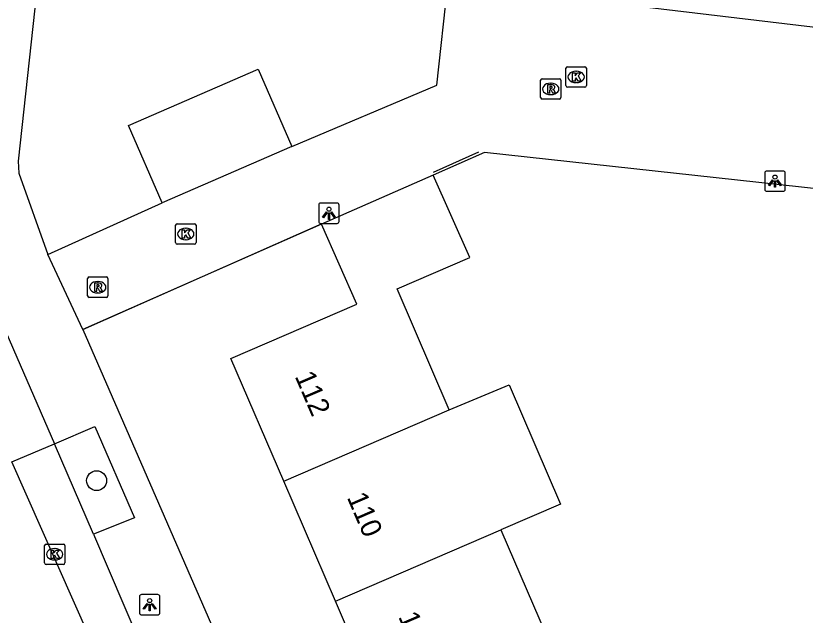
# Model space of a CAD drawing. Extents: x 162026 to 163499, y 387297 to 388169.
# Drawn here: x 162202.16 to 162240.89, y 387912.47 to 387941.9 of the extents above; entities that cross this region are included whole.
import ezdxf

# ---------------------------------------------------------------- set-up
doc = ezdxf.new("R2010")
doc.units = 0
for name, color, linetype in [('IMGEO_Boom', 7, 'Continuous'), ('IMGEO_Kolk', 7, 'Continuous'), ('IMGEO_Lichtpunt', 7, 'Continuous'), ('IMGEO_Muur', 7, 'Continuous'), ('IMGEO_Pand', 7, 'Continuous'), ('IMGEO_Pand_nummerreeks', 7, 'Continuous'), ('IMGEO_Parkeervlak_open', 7, 'Continuous'), ('IMGEO_Rijbaan_lokaal_open', 7, 'Continuous'), ('IMGEO_Rioolput', 7, 'Continuous'), ('IMGEO_Voetpad_open', 7, 'Continuous')]:
    doc.layers.add(name, color=color, linetype=linetype)

msp = doc.modelspace()

# ---------------------------------------------------------------- linework, layer by layer
at = {"layer": 'IMGEO_Boom'}
msp.add_circle((162206.125, 387919.078), 0.489, dxfattribs=at)
at = {"layer": 'IMGEO_Kolk'}
for p, q in [((162229.153, 387938.473), (162229.153, 387939.325)), ((162229.228, 387939.399), (162230.08, 387939.399)), ((162230.154, 387939.325), (162230.154, 387938.473)), ((162229.641, 387939.179), (162229.666, 387939.179)), ((162229.664, 387938.619), (162229.639, 387938.619)), ((162230.08, 387938.399), (162229.228, 387938.399)), ((162210.001, 387930.763), (162210.001, 387931.615)), ((162210.076, 387931.689), (162210.928, 387931.689)), ((162211.002, 387931.615), (162211.002, 387930.763)), ((162210.489, 387931.469), (162210.514, 387931.469)), ((162210.512, 387930.909), (162210.487, 387930.909)), ((162210.928, 387930.689), (162210.076, 387930.689)), ((162203.57, 387915.037), (162203.57, 387915.889)), ((162203.645, 387915.963), (162204.497, 387915.963)), ((162204.058, 387915.743), (162204.083, 387915.743)), ((162204.571, 387915.889), (162204.571, 387915.037)), ((162204.497, 387914.963), (162203.645, 387914.963)), ((162204.081, 387915.183), (162204.056, 387915.183))]:
    msp.add_line(p, q, dxfattribs=at)
for points in [[(162229.153, 387938.473), (162229.153, 387939.325)], [(162229.228, 387939.399), (162230.08, 387939.399)], [(162230.154, 387939.325), (162230.154, 387938.473)], [(162229.474, 387939.099), (162229.597, 387939.099), (162229.597, 387938.948), (162229.727, 387939.099), (162229.891, 387939.099), (162229.745, 387938.948), (162229.898, 387938.699), (162229.746, 387938.699), (162229.661, 387938.863), (162229.597, 387938.796), (162229.597, 387938.699), (162229.474, 387938.699), (162229.474, 387939.099)], [(162230.08, 387938.399), (162229.228, 387938.399)], [(162210.001, 387930.763), (162210.001, 387931.615)], [(162210.076, 387931.689), (162210.928, 387931.689)], [(162211.002, 387931.615), (162211.002, 387930.763)], [(162210.322, 387931.389), (162210.445, 387931.389), (162210.445, 387931.238), (162210.575, 387931.389), (162210.739, 387931.389), (162210.593, 387931.238), (162210.746, 387930.989), (162210.594, 387930.989), (162210.509, 387931.153), (162210.445, 387931.086), (162210.445, 387930.989), (162210.322, 387930.989), (162210.322, 387931.389)], [(162210.928, 387930.689), (162210.076, 387930.689)], [(162203.57, 387915.037), (162203.57, 387915.889)], [(162203.645, 387915.963), (162204.497, 387915.963)], [(162203.891, 387915.663), (162204.014, 387915.663), (162204.014, 387915.512), (162204.144, 387915.663), (162204.308, 387915.663), (162204.162, 387915.512), (162204.315, 387915.263), (162204.163, 387915.263), (162204.078, 387915.427), (162204.014, 387915.36), (162204.014, 387915.263), (162203.891, 387915.263), (162203.891, 387915.663)], [(162204.571, 387915.889), (162204.571, 387915.037)], [(162204.497, 387914.963), (162203.645, 387914.963)]]:
    msp.add_lwpolyline(points, dxfattribs=at)
for centre, start, end in [((162229.23, 387939.323), 91.552, 178.448), ((162229.23, 387939.323), 91.552, 178.448), ((162230.078, 387939.323), 1.552, 88.448), ((162230.078, 387939.323), 1.552, 88.448), ((162229.23, 387938.475), 181.552, 268.448), ((162229.23, 387938.475), 181.552, 268.448), ((162230.078, 387938.475), 271.552, 358.448), ((162230.078, 387938.475), 271.552, 358.448), ((162210.078, 387931.613), 91.552, 178.448), ((162210.078, 387931.613), 91.552, 178.448), ((162210.926, 387931.613), 1.552, 88.448), ((162210.926, 387931.613), 1.552, 88.448), ((162210.078, 387930.765), 181.552, 268.448), ((162210.078, 387930.765), 181.552, 268.448), ((162210.926, 387930.765), 271.552, 358.448), ((162210.926, 387930.765), 271.552, 358.448), ((162203.647, 387915.887), 91.552, 178.448), ((162203.647, 387915.887), 91.552, 178.448), ((162204.495, 387915.887), 1.552, 88.448), ((162204.495, 387915.887), 1.552, 88.448), ((162203.647, 387915.039), 181.552, 268.448), ((162203.647, 387915.039), 181.552, 268.448), ((162204.495, 387915.039), 271.552, 358.448), ((162204.495, 387915.039), 271.552, 358.448)]:
    msp.add_arc(centre, 0.0765, start, end, dxfattribs=at)
for centre, major_axis, ratio, start_param, end_param in [((162229.64, 387938.899), (-0.387, 0.002), 0.722429, 4.712389, 7.853982), ((162229.665, 387938.899), (-0.39, 0.002), 0.717154, 1.570796, 4.712389), ((162210.488, 387931.189), (-0.387, 0.002), 0.722429, 4.712389, 7.853982), ((162210.513, 387931.189), (-0.39, 0.002), 0.717154, 1.570796, 4.712389), ((162204.057, 387915.463), (-0.387, 0.002), 0.722429, 4.712389, 7.853982), ((162204.082, 387915.463), (-0.39, 0.002), 0.717154, 1.570796, 4.712389)]:
    msp.add_ellipse(centre, major_axis=major_axis, ratio=ratio, start_param=start_param, end_param=end_param, dxfattribs=at)
at = {"layer": 'IMGEO_Lichtpunt'}
for p, q in [((162239.814, 387934.281), (162239.006, 387934.281)), ((162239.814, 387934.281), (162239.006, 387934.281)), ((162238.912, 387934.186), (162238.912, 387933.379)), ((162238.912, 387934.186), (162238.912, 387933.379)), ((162239.908, 387933.379), (162239.908, 387934.186)), ((162239.908, 387933.379), (162239.908, 387934.186)), ((162239.006, 387933.285), (162239.814, 387933.285)), ((162239.006, 387933.285), (162239.814, 387933.285)), ((162217.927, 387932.706), (162217.119, 387932.706)), ((162217.927, 387932.706), (162217.119, 387932.706)), ((162217.025, 387932.611), (162217.025, 387931.804)), ((162217.025, 387932.611), (162217.025, 387931.804)), ((162218.021, 387931.804), (162218.021, 387932.611)), ((162218.021, 387931.804), (162218.021, 387932.611)), ((162217.119, 387931.71), (162217.927, 387931.71)), ((162217.119, 387931.71), (162217.927, 387931.71)), ((162208.23, 387913.389), (162208.23, 387912.582)), ((162208.23, 387913.389), (162208.23, 387912.582)), ((162209.132, 387913.484), (162208.324, 387913.484)), ((162209.132, 387913.484), (162208.324, 387913.484)), ((162209.226, 387912.582), (162209.226, 387913.389)), ((162209.226, 387912.582), (162209.226, 387913.389)), ((162208.324, 387912.488), (162209.132, 387912.488)), ((162208.324, 387912.488), (162209.132, 387912.488))]:
    msp.add_line(p, q, dxfattribs=at)
for points in [[(162239.286, 387933.85), (162239.325, 387933.822), (162239.137, 387933.56), (162239.099, 387933.587), (162239.286, 387933.85)], [(162239.498, 387933.822), (162239.536, 387933.849), (162239.723, 387933.587), (162239.684, 387933.559), (162239.498, 387933.822)], [(162239.388, 387933.802), (162239.435, 387933.802), (162239.435, 387933.48), (162239.388, 387933.48), (162239.388, 387933.802)], [(162217.399, 387932.275), (162217.438, 387932.247), (162217.25, 387931.985), (162217.212, 387932.012), (162217.399, 387932.275)], [(162217.501, 387932.227), (162217.548, 387932.227), (162217.548, 387931.905), (162217.501, 387931.905), (162217.501, 387932.227)], [(162217.611, 387932.247), (162217.649, 387932.274), (162217.836, 387932.012), (162217.797, 387931.984), (162217.611, 387932.247)], [(162208.604, 387913.053), (162208.643, 387913.025), (162208.455, 387912.763), (162208.417, 387912.79), (162208.604, 387913.053)], [(162208.706, 387913.005), (162208.753, 387913.005), (162208.753, 387912.683), (162208.706, 387912.683), (162208.706, 387913.005)], [(162208.816, 387913.025), (162208.854, 387913.052), (162209.041, 387912.79), (162209.002, 387912.762), (162208.816, 387913.025)]]:
    msp.add_lwpolyline(points, dxfattribs=at)
for centre in [(162239.411, 387933.984), (162217.524, 387932.409), (162208.729, 387913.187)]:
    msp.add_circle(centre, 0.0994, dxfattribs=at)
for centre, start, end in [((162239.006, 387934.186), 90, 180), ((162239.006, 387934.186), 90, 180), ((162239.814, 387934.186), 0, 90), ((162239.814, 387934.186), 0, 90), ((162239.006, 387933.379), 180, 270), ((162239.006, 387933.379), 180, 270), ((162239.814, 387933.379), 270, 0), ((162239.814, 387933.379), 270, 360), ((162217.119, 387932.611), 90, 180), ((162217.119, 387932.611), 90, 180), ((162217.927, 387932.611), 0, 90), ((162217.927, 387932.611), 0, 90), ((162217.119, 387931.804), 180, 270), ((162217.119, 387931.804), 180, 270), ((162217.927, 387931.804), 270, 0), ((162217.927, 387931.804), 270, 360), ((162208.324, 387913.389), 90, 180), ((162208.324, 387913.389), 90, 180), ((162209.132, 387913.389), 0, 90), ((162209.132, 387913.389), 0, 90), ((162208.324, 387912.582), 180, 270), ((162208.324, 387912.582), 180, 270), ((162209.132, 387912.582), 270, 0), ((162209.132, 387912.582), 270, 360)]:
    msp.add_arc(centre, 0.0946, start, end, dxfattribs=at)
at = {"layer": 'IMGEO_Muur'}
for points in [[(162222.649, 387934.224), (162224.882, 387935.222)], [(162205.445, 387926.498), (162217.184, 387931.704)]]:
    msp.add_lwpolyline(points, dxfattribs=at)
at = {"layer": 'IMGEO_Pand'}
for points in [[(162209.349, 387932.711), (162207.692, 387936.518), (162214.052, 387939.286), (162215.708, 387935.479)], [(162215.708, 387935.479), (162209.349, 387932.711)], [(162222.631, 387934.077), (162217.151, 387931.664)], [(162223.427, 387922.55), (162220.869, 387928.498), (162224.435, 387930.031), (162222.631, 387934.077)], [(162215.306, 387919.056), (162212.716, 387925.079), (162218.89, 387927.735), (162217.151, 387931.664)], [(162223.427, 387922.55), (162226.365, 387923.783), (162228.885, 387917.923), (162225.961, 387916.658)], [(162215.306, 387919.056), (162223.427, 387922.55)], [(162217.84, 387913.165), (162215.306, 387919.056)], [(162217.84, 387913.165), (162225.961, 387916.658)], [(162225.961, 387916.658), (162228.49, 387910.779)], [(162220.369, 387907.286), (162217.84, 387913.165)]]:
    msp.add_lwpolyline(points, dxfattribs=at)
at = {"layer": 'IMGEO_Parkeervlak_open'}
msp.add_lwpolyline([(162205.968, 387916.454), (162204.063, 387920.878)], dxfattribs=at)
at = {"layer": 'IMGEO_Rijbaan_lokaal_open'}
for points in [[(162230.797, 387942.603), (162245.241, 387940.89), (162249.184, 387940.423), (162249.731, 387944.997), (162250.767, 387953.668)], [(162215.708, 387935.479), (162222.811, 387938.496), (162223.356, 387943.457)], [(162243.847, 387933.152), (162225.162, 387935.191), (162222.631, 387934.077)], [(162203.737, 387930.179), (162209.349, 387932.711)], [(162217.151, 387931.664), (162205.445, 387926.498)], [(162199.97, 387930.267), (162204.063, 387920.878)], [(162205.445, 387926.498), (162203.737, 387930.179)], [(162201.966, 387919.996), (162204.063, 387920.878)], [(162214.74, 387891.15), (162214.557, 387891.577), (162214.133, 387892.535), (162201.966, 387919.996)]]:
    msp.add_lwpolyline(points, dxfattribs=at)
at = {"layer": 'IMGEO_Rioolput'}
for p, q in [((162227.908, 387937.886), (162227.908, 387938.738)), ((162227.983, 387938.812), (162228.835, 387938.812)), ((162228.396, 387938.592), (162228.421, 387938.592)), ((162228.909, 387938.738), (162228.909, 387937.886)), ((162228.835, 387937.812), (162227.983, 387937.812)), ((162228.419, 387938.032), (162228.394, 387938.032)), ((162205.681, 387928.151), (162205.681, 387929.003)), ((162205.756, 387929.077), (162206.608, 387929.077)), ((162206.169, 387928.857), (162206.194, 387928.857)), ((162206.682, 387929.003), (162206.682, 387928.151)), ((162206.608, 387928.077), (162205.756, 387928.077)), ((162206.192, 387928.297), (162206.167, 387928.297))]:
    msp.add_line(p, q, dxfattribs=at)
for points in [[(162227.908, 387937.886), (162227.908, 387938.738)], [(162227.983, 387938.812), (162228.835, 387938.812)], [(162228.497, 387938.51), (162228.245, 387938.512), (162228.245, 387938.112)], [(162228.909, 387938.738), (162228.909, 387937.886)], [(162228.245, 387938.112), (162228.369, 387938.112), (162228.369, 387938.274), (162228.38, 387938.274)], [(162228.423, 387938.431), (162228.369, 387938.431), (162228.369, 387938.35)], [(162228.369, 387938.35), (162228.421, 387938.35)], [(162228.427, 387938.245), (162228.498, 387938.112), (162228.638, 387938.112), (162228.573, 387938.238)], [(162228.835, 387937.812), (162227.983, 387937.812)], [(162205.681, 387928.151), (162205.681, 387929.003)], [(162205.756, 387929.077), (162206.608, 387929.077)], [(162206.682, 387929.003), (162206.682, 387928.151)], [(162206.27, 387928.775), (162206.018, 387928.777), (162206.018, 387928.377)], [(162206.018, 387928.377), (162206.142, 387928.377), (162206.142, 387928.539), (162206.153, 387928.539)], [(162206.196, 387928.696), (162206.142, 387928.696), (162206.142, 387928.615)], [(162206.142, 387928.615), (162206.194, 387928.615)], [(162206.2, 387928.51), (162206.271, 387928.377), (162206.411, 387928.377), (162206.346, 387928.503)], [(162206.608, 387928.077), (162205.756, 387928.077)]]:
    msp.add_lwpolyline(points, dxfattribs=at)
for centre, radius, start, end in [((162227.985, 387938.736), 0.0765, 91.552, 178.448), ((162227.985, 387938.736), 0.0765, 91.552, 178.448), ((162228.496, 387938.4), 0.109, 350.3612, 89.416), ((162228.833, 387938.736), 0.0765, 1.552, 88.448), ((162228.833, 387938.736), 0.0765, 1.552, 88.448), ((162228.379, 387938.221), 0.0533, 26.0293, 88.6989), ((162228.405, 387938.539), 0.19, 274.7715, 282.9687), ((162228.429, 387938.335), 0.0964, 77.0061, 93.1865), ((162228.443, 387938.392), 0.0378, 276.6634, 79.6772), ((162228.494, 387938.4), 0.112, 277.5842, 350.9817), ((162228.478, 387938.185), 0.108, 29.5134, 73.7905), ((162227.985, 387937.888), 0.0765, 181.552, 268.448), ((162227.985, 387937.888), 0.0765, 181.552, 268.448), ((162228.833, 387937.888), 0.0765, 271.552, 358.448), ((162228.833, 387937.888), 0.0765, 271.552, 358.448), ((162205.758, 387929.001), 0.0765, 91.552, 178.448), ((162205.758, 387929.001), 0.0765, 91.552, 178.448), ((162206.606, 387929.001), 0.0765, 1.552, 88.448), ((162206.606, 387929.001), 0.0765, 1.552, 88.448), ((162206.152, 387928.486), 0.0533, 26.0293, 88.6989), ((162206.178, 387928.804), 0.19, 274.7715, 282.9687), ((162206.202, 387928.6), 0.0964, 77.0061, 93.1865), ((162206.216, 387928.657), 0.0378, 276.6634, 79.6772), ((162206.269, 387928.665), 0.109, 350.3612, 89.416), ((162206.267, 387928.665), 0.112, 277.5842, 350.9817), ((162206.251, 387928.45), 0.108, 29.5134, 73.7905), ((162205.758, 387928.153), 0.0765, 181.552, 268.448), ((162205.758, 387928.153), 0.0765, 181.552, 268.448), ((162206.606, 387928.153), 0.0765, 271.552, 358.448), ((162206.606, 387928.153), 0.0765, 271.552, 358.448)]:
    msp.add_arc(centre, radius, start, end, dxfattribs=at)
for centre, major_axis, ratio, start_param, end_param in [((162228.395, 387938.312), (-0.387, 0.002), 0.722429, 4.712389, 7.853982), ((162228.42, 387938.312), (-0.39, 0.002), 0.717154, 1.570796, 4.712389), ((162206.168, 387928.577), (-0.387, 0.002), 0.722429, 4.712389, 7.853982), ((162206.193, 387928.577), (-0.39, 0.002), 0.717154, 1.570796, 4.712389)]:
    msp.add_ellipse(centre, major_axis=major_axis, ratio=ratio, start_param=start_param, end_param=end_param, dxfattribs=at)
at = {"layer": 'IMGEO_Voetpad_open'}
for points in [[(162203.528, 387946.354), (162202.28, 387934.764), (162202.317, 387934.183), (162203.737, 387930.179)], [(162205.445, 387926.498), (162231.603, 387866.429)], [(162204.063, 387920.878), (162206.039, 387921.731), (162207.985, 387917.244), (162205.968, 387916.454)], [(162205.968, 387916.454), (162208.23, 387911.16)]]:
    msp.add_lwpolyline(points, dxfattribs=at)

# ---------------------------------------------------------------- texts
at = {"layer": 'IMGEO_Pand_nummerreeks'}
for s, rotation, p in [('112', 293.2733, (162215.835, 387924.205)), ('110', 293.2717, (162218.393, 387918.259)), ('108', 293.2717, (162220.912, 387912.401))]:
    msp.add_text(s, height=1, rotation=rotation, dxfattribs=at).set_placement(p)

doc.saveas('drawing.dxf')
